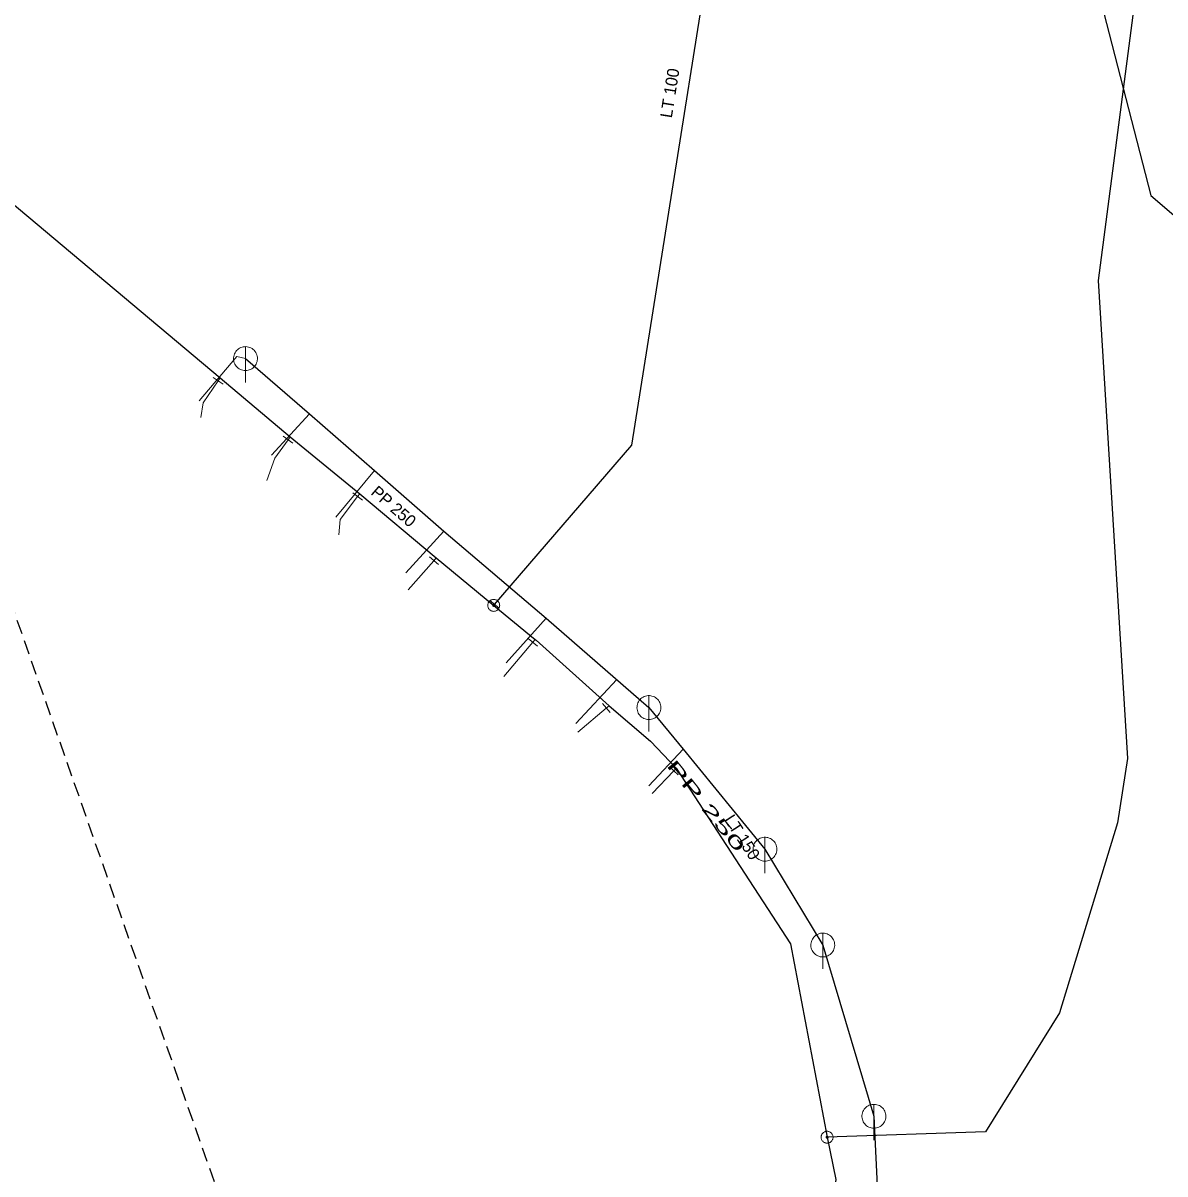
# Model space of a CAD drawing. Extents: x -659250 to -657316, y -997555 to -993684.
# Drawn here: x -658756.5 to -658660.9, y -994925.7 to -994829.4 of the extents above; entities that cross this region are included whole.
import ezdxf

# ---------------------------------------------------------------- set-up
doc = ezdxf.new("R2010")
doc.units = 0
doc.header["$LTSCALE"] = 0.4
doc.linetypes.add('MEDIUM_DASHED', pattern=[4.5, 3, -1.5])
doc.layers.add('1', color=7, linetype='Continuous')
for name, color, linetype, lineweight in [('11', 7, 'Continuous', 13), ('13', 7, 'Continuous', 13), ('14', 7, 'Continuous', 25), ('17', 7, 'Continuous', 25), ('22', 7, 'Continuous', 13), ('34', 7, 'Continuous', 13), ('47', 7, 'Continuous', 13), ('63', 7, 'MEDIUM_DASHED', 25)]:
    doc.layers.add(name, color=color, linetype=linetype, lineweight=lineweight)

msp = doc.modelspace()

# ---------------------------------------------------------------- linework, layer by layer
at = {"layer": '11'}
for p, q in [((-658735.68, -994865.6), (-658732.5, -994862.149)), ((-658730.28, -994870.78), (-658727.039, -994866.89)), ((-658724.43, -994875.46), (-658721.237, -994871.947)), ((-658716.03, -994882.969), (-658712.682, -994879.243)), ((-658706.775, -994884.377), (-658710.19, -994888.059)), ((-658704.1, -994893.28), (-658701.228, -994890.199))]:
    msp.add_line(p, q, dxfattribs=at)
msp.add_lwpolyline([(-658741.719, -994861.05), (-658738.559, -994857.35), (-658737.85, -994857.52)], dxfattribs=at)
at = {"layer": '13'}
for p, q in [((-658722.078, -994874.43), (-658724.219, -994876.859)), ((-658713.803, -994881.249), (-658716.219, -994884.129)), ((-658707.648, -994886.764), (-658710.03, -994888.789)), ((-658702.006, -994892.017), (-658703.8, -994893.91))]:
    msp.add_line(p, q, dxfattribs=at)
for points in [[(-658740.128, -994859.373), (-658741.39, -994861.234), (-658741.59, -994862.44)], [(-658734.276, -994864.307), (-658735.39, -994865.842), (-658736.05, -994867.719)], [(-658728.461, -994869.063), (-658729.916, -994870.975), (-658730.03, -994872.26)]]:
    msp.add_lwpolyline(points, dxfattribs=at)
at = {"layer": '14', "lineweight": 13}
for p, q in [((-658739.96, -994859.124), (-658740.128, -994859.373)), ((-658734.1, -994864.064), (-658734.276, -994864.307)), ((-658728.28, -994868.824), (-658728.461, -994869.063)), ((-658721.879, -994874.204), (-658722.078, -994874.43)), ((-658717.07, -994878.168), (-658717.005, -994878.092)), ((-658713.611, -994881.019), (-658713.803, -994881.249)), ((-658707.42, -994886.57), (-658707.648, -994886.764)), ((-658701.8, -994891.8), (-658702.006, -994892.017))]:
    msp.add_line(p, q, dxfattribs=at)
at = {"layer": '14'}
msp.add_line((-658685.25, -994920.92), (-658684.84, -994929.449), dxfattribs=at)
for points in [[(-658737.85, -994857.52), (-658732.5, -994862.149), (-658727.039, -994866.89), (-658721.237, -994871.947), (-658712.682, -994879.243), (-658704.079, -994886.719)], [(-658704.079, -994886.719), (-658701.228, -994890.199), (-658694.37, -994898.57)], [(-658694.37, -994898.57), (-658689.53, -994906.59), (-658685.25, -994920.92)]]:
    msp.add_lwpolyline(points, dxfattribs=at)
at = {"layer": '17'}
for points in [[(-658702.57, -994435.41), (-658705.199, -994436.353), (-658712.71, -994474.592), (-658701.204, -994536.879), (-658692.771, -994555.022), (-658691.405, -994641.16), (-658677.627, -994701.215), (-658678.449, -994734.261), (-658664.614, -994780.175), (-658662.973, -994794.498), (-658662.386, -994819.574), (-658666.489, -994850.982), (-658664.028, -994890.978), (-658664.848, -994896.368), (-658669.708, -994912.272), (-658675.921, -994922.23), (-658689.166, -994922.67)], [(-658833.469, -994620.44), (-658786.396, -994668.37), (-658672.524, -994803.272), (-658662.072, -994843.868), (-658638.662, -994863.933)], [(-658944.471, -994767.595), (-658929.982, -994769.565), (-658923.066, -994770.504), (-658908.315, -994773.538), (-658887.522, -994777.767), (-658868.1, -994785.67), (-658835.011, -994798.656), (-658813.55, -994808.542), (-658788.769, -994821.229), (-658774.498, -994830.239), (-658768.436, -994835.283), (-658761.23, -994841.315), (-658739.96, -994859.124), (-658734.1, -994864.064), (-658728.28, -994868.824), (-658721.879, -994874.204), (-658717.07, -994878.168)], [(-658717.005, -994878.092), (-658705.507, -994864.76), (-658695.942, -994804.489)], [(-658717.07, -994878.168), (-658713.611, -994881.019), (-658713.523, -994881.091), (-658707.42, -994886.57), (-658703.946, -994889.54), (-658701.8, -994891.8), (-658692.227, -994906.488), (-658689.166, -994922.67)], [(-658689.166, -994922.67), (-658688.447, -994926.223), (-658691.355, -994947.704), (-658699.204, -994963.84), (-658705.204, -994963.234), (-658707.419, -994974.603)]]:
    msp.add_lwpolyline(points, dxfattribs=at)
at = {"layer": '22'}
for p, q in [((-658737.85, -994859.52), (-658737.849, -994856.52)), ((-658704.08, -994888.72), (-658704.079, -994885.72)), ((-658694.37, -994900.57), (-658694.369, -994897.57)), ((-658689.53, -994908.59), (-658689.529, -994905.59)), ((-658685.25, -994922.92), (-658685.249, -994919.92))]:
    msp.add_line(p, q, dxfattribs=at)
for points in [[(-658736.85, -994857.52), (-658736.855, -994857.411), (-658736.873, -994857.303), (-658736.903, -994857.197), (-658736.943, -994857.096), (-658736.995, -994856.999), (-658737.057, -994856.909), (-658737.129, -994856.826), (-658737.209, -994856.752), (-658737.297, -994856.686), (-658737.391, -994856.631), (-658737.491, -994856.586), (-658737.596, -994856.553), (-658737.703, -994856.531), (-658737.812, -994856.521), (-658737.922, -994856.523), (-658738.03, -994856.537), (-658738.137, -994856.562), (-658738.24, -994856.599), (-658738.338, -994856.648), (-658738.43, -994856.706), (-658738.516, -994856.775), (-658738.593, -994856.852), (-658738.662, -994856.938), (-658738.721, -994857.03), (-658738.769, -994857.128), (-658738.806, -994857.231), (-658738.832, -994857.338), (-658738.846, -994857.446), (-658738.849, -994857.556), (-658738.839, -994857.665), (-658738.818, -994857.772), (-658738.784, -994857.876), (-658738.74, -994857.976), (-658738.685, -994858.071), (-658738.619, -994858.159), (-658738.545, -994858.239), (-658738.462, -994858.311), (-658738.372, -994858.373), (-658738.276, -994858.425), (-658738.174, -994858.466), (-658738.069, -994858.496), (-658737.961, -994858.514), (-658737.851, -994858.52), (-658737.742, -994858.514), (-658737.634, -994858.496), (-658737.529, -994858.467), (-658737.427, -994858.426), (-658737.33, -994858.374), (-658737.24, -994858.312), (-658737.157, -994858.241), (-658737.082, -994858.161), (-658737.017, -994858.073), (-658736.961, -994857.979), (-658736.917, -994857.879), (-658736.883, -994857.775), (-658736.861, -994857.667), (-658736.851, -994857.558)], [(-658703.08, -994886.72), (-658703.085, -994886.611), (-658703.103, -994886.503), (-658703.133, -994886.397), (-658703.173, -994886.296), (-658703.225, -994886.199), (-658703.287, -994886.109), (-658703.359, -994886.026), (-658703.439, -994885.952), (-658703.527, -994885.886), (-658703.621, -994885.831), (-658703.721, -994885.786), (-658703.826, -994885.753), (-658703.933, -994885.731), (-658704.042, -994885.721), (-658704.152, -994885.723), (-658704.26, -994885.737), (-658704.367, -994885.762), (-658704.47, -994885.799), (-658704.568, -994885.848), (-658704.66, -994885.906), (-658704.746, -994885.975), (-658704.823, -994886.052), (-658704.892, -994886.138), (-658704.951, -994886.23), (-658704.999, -994886.328), (-658705.036, -994886.431), (-658705.062, -994886.538), (-658705.076, -994886.646), (-658705.079, -994886.756), (-658705.069, -994886.865), (-658705.048, -994886.972), (-658705.014, -994887.076), (-658704.97, -994887.176), (-658704.915, -994887.271), (-658704.849, -994887.359), (-658704.775, -994887.439), (-658704.692, -994887.511), (-658704.602, -994887.573), (-658704.506, -994887.625), (-658704.404, -994887.666), (-658704.299, -994887.696), (-658704.191, -994887.714), (-658704.081, -994887.72), (-658703.972, -994887.714), (-658703.864, -994887.696), (-658703.759, -994887.667), (-658703.657, -994887.626), (-658703.56, -994887.574), (-658703.47, -994887.512), (-658703.387, -994887.441), (-658703.312, -994887.361), (-658703.247, -994887.273), (-658703.191, -994887.179), (-658703.147, -994887.079), (-658703.113, -994886.975), (-658703.091, -994886.867), (-658703.081, -994886.758)], [(-658693.37, -994898.57), (-658693.375, -994898.461), (-658693.393, -994898.353), (-658693.423, -994898.247), (-658693.463, -994898.146), (-658693.515, -994898.049), (-658693.577, -994897.959), (-658693.649, -994897.876), (-658693.729, -994897.802), (-658693.817, -994897.736), (-658693.911, -994897.681), (-658694.011, -994897.636), (-658694.116, -994897.603), (-658694.223, -994897.581), (-658694.332, -994897.571), (-658694.442, -994897.573), (-658694.55, -994897.587), (-658694.657, -994897.612), (-658694.76, -994897.649), (-658694.858, -994897.698), (-658694.95, -994897.756), (-658695.036, -994897.825), (-658695.113, -994897.902), (-658695.182, -994897.988), (-658695.241, -994898.08), (-658695.289, -994898.178), (-658695.326, -994898.281), (-658695.352, -994898.388), (-658695.366, -994898.496), (-658695.369, -994898.606), (-658695.359, -994898.715), (-658695.338, -994898.822), (-658695.304, -994898.926), (-658695.26, -994899.026), (-658695.205, -994899.121), (-658695.139, -994899.209), (-658695.065, -994899.289), (-658694.982, -994899.361), (-658694.892, -994899.423), (-658694.796, -994899.475), (-658694.694, -994899.516), (-658694.589, -994899.546), (-658694.481, -994899.564), (-658694.371, -994899.57), (-658694.262, -994899.564), (-658694.154, -994899.546), (-658694.049, -994899.517), (-658693.947, -994899.476), (-658693.85, -994899.424), (-658693.76, -994899.362), (-658693.677, -994899.291), (-658693.602, -994899.211), (-658693.537, -994899.123), (-658693.481, -994899.029), (-658693.437, -994898.929), (-658693.403, -994898.825), (-658693.381, -994898.717), (-658693.371, -994898.608)], [(-658688.53, -994906.59), (-658688.535, -994906.481), (-658688.553, -994906.373), (-658688.583, -994906.267), (-658688.623, -994906.166), (-658688.675, -994906.069), (-658688.737, -994905.979), (-658688.809, -994905.896), (-658688.889, -994905.822), (-658688.977, -994905.756), (-658689.071, -994905.701), (-658689.171, -994905.656), (-658689.276, -994905.623), (-658689.383, -994905.601), (-658689.492, -994905.591), (-658689.602, -994905.593), (-658689.71, -994905.607), (-658689.817, -994905.632), (-658689.92, -994905.669), (-658690.018, -994905.718), (-658690.11, -994905.776), (-658690.196, -994905.845), (-658690.273, -994905.922), (-658690.342, -994906.008), (-658690.401, -994906.1), (-658690.449, -994906.198), (-658690.486, -994906.301), (-658690.512, -994906.408), (-658690.526, -994906.516), (-658690.529, -994906.626), (-658690.519, -994906.735), (-658690.498, -994906.842), (-658690.464, -994906.946), (-658690.42, -994907.046), (-658690.365, -994907.141), (-658690.299, -994907.229), (-658690.225, -994907.309), (-658690.142, -994907.381), (-658690.052, -994907.443), (-658689.956, -994907.495), (-658689.854, -994907.536), (-658689.749, -994907.566), (-658689.641, -994907.584), (-658689.531, -994907.59), (-658689.422, -994907.584), (-658689.314, -994907.566), (-658689.209, -994907.537), (-658689.107, -994907.496), (-658689.01, -994907.444), (-658688.92, -994907.382), (-658688.837, -994907.311), (-658688.762, -994907.231), (-658688.697, -994907.143), (-658688.641, -994907.049), (-658688.597, -994906.949), (-658688.563, -994906.845), (-658688.541, -994906.737), (-658688.531, -994906.628)], [(-658684.25, -994920.92), (-658684.255, -994920.811), (-658684.273, -994920.703), (-658684.303, -994920.597), (-658684.343, -994920.496), (-658684.395, -994920.399), (-658684.457, -994920.309), (-658684.529, -994920.226), (-658684.609, -994920.152), (-658684.697, -994920.086), (-658684.791, -994920.031), (-658684.891, -994919.986), (-658684.996, -994919.953), (-658685.103, -994919.931), (-658685.212, -994919.921), (-658685.322, -994919.923), (-658685.43, -994919.937), (-658685.537, -994919.962), (-658685.64, -994919.999), (-658685.738, -994920.048), (-658685.83, -994920.106), (-658685.916, -994920.175), (-658685.993, -994920.252), (-658686.062, -994920.338), (-658686.121, -994920.43), (-658686.169, -994920.528), (-658686.206, -994920.631), (-658686.232, -994920.738), (-658686.246, -994920.846), (-658686.249, -994920.956), (-658686.239, -994921.065), (-658686.218, -994921.172), (-658686.184, -994921.276), (-658686.14, -994921.376), (-658686.085, -994921.471), (-658686.019, -994921.559), (-658685.945, -994921.639), (-658685.862, -994921.711), (-658685.772, -994921.773), (-658685.676, -994921.825), (-658685.574, -994921.866), (-658685.469, -994921.896), (-658685.361, -994921.914), (-658685.251, -994921.92), (-658685.142, -994921.914), (-658685.034, -994921.896), (-658684.929, -994921.867), (-658684.827, -994921.826), (-658684.73, -994921.774), (-658684.64, -994921.712), (-658684.557, -994921.641), (-658684.482, -994921.561), (-658684.417, -994921.473), (-658684.361, -994921.379), (-658684.317, -994921.279), (-658684.283, -994921.175), (-658684.261, -994921.067), (-658684.251, -994920.958)]]:
    msp.add_lwpolyline(points, close=True, dxfattribs=at)
at = {"layer": '34'}
for p, q in [((-658739.713, -994859.653), (-658740.541, -994859.092)), ((-658733.871, -994864.6), (-658734.68, -994864.012)), ((-658728.062, -994869.365), (-658728.858, -994868.759)), ((-658721.702, -994874.76), (-658722.452, -994874.099)), ((-658717.386, -994877.769), (-658716.623, -994878.415)), ((-658713.419, -994881.569), (-658714.185, -994880.927)), ((-658707.323, -994887.144), (-658707.971, -994886.382)), ((-658701.642, -994892.36), (-658702.368, -994891.672))]:
    msp.add_line(p, q, dxfattribs=at)
at = {"layer": '47'}
for points in [[(-658716.57, -994878.168), (-658716.573, -994878.115), (-658716.581, -994878.063), (-658716.595, -994878.014), (-658716.612, -994877.965), (-658716.637, -994877.918), (-658716.666, -994877.874), (-658716.698, -994877.833), (-658716.735, -994877.796), (-658716.776, -994877.764), (-658716.82, -994877.735), (-658716.867, -994877.71), (-658716.916, -994877.693), (-658716.965, -994877.679), (-658717.017, -994877.671), (-658717.07, -994877.668), (-658717.122, -994877.671), (-658717.174, -994877.679), (-658717.225, -994877.693), (-658717.272, -994877.71), (-658717.32, -994877.735), (-658717.364, -994877.764), (-658717.404, -994877.796), (-658717.441, -994877.833), (-658717.475, -994877.874), (-658717.502, -994877.918), (-658717.527, -994877.965), (-658717.546, -994878.014), (-658717.558, -994878.063), (-658717.566, -994878.115), (-658717.57, -994878.168), (-658717.566, -994878.22), (-658717.558, -994878.272), (-658717.546, -994878.323), (-658717.527, -994878.37), (-658717.502, -994878.418), (-658717.475, -994878.462), (-658717.441, -994878.502), (-658717.404, -994878.539), (-658717.364, -994878.573), (-658717.32, -994878.6), (-658717.272, -994878.625), (-658717.225, -994878.644), (-658717.174, -994878.656), (-658717.122, -994878.664), (-658717.07, -994878.668), (-658717.017, -994878.664), (-658716.965, -994878.656), (-658716.916, -994878.644), (-658716.867, -994878.625), (-658716.82, -994878.6), (-658716.776, -994878.573), (-658716.735, -994878.539), (-658716.698, -994878.502), (-658716.666, -994878.462), (-658716.637, -994878.418), (-658716.612, -994878.37), (-658716.595, -994878.323), (-658716.581, -994878.272), (-658716.573, -994878.22)], [(-658716.987, -994878.168), (-658716.987, -994878.159), (-658716.99, -994878.151), (-658716.992, -994878.142), (-658716.995, -994878.134), (-658716.999, -994878.127), (-658717.004, -994878.12), (-658717.009, -994878.112), (-658717.014, -994878.107), (-658717.022, -994878.102), (-658717.029, -994878.097), (-658717.036, -994878.093), (-658717.044, -994878.09), (-658717.053, -994878.088), (-658717.061, -994878.085), (-658717.07, -994878.085), (-658717.078, -994878.085), (-658717.087, -994878.088), (-658717.095, -994878.09), (-658717.103, -994878.093), (-658717.11, -994878.097), (-658717.117, -994878.102), (-658717.125, -994878.107), (-658717.13, -994878.112), (-658717.137, -994878.12), (-658717.141, -994878.127), (-658717.144, -994878.134), (-658717.147, -994878.142), (-658717.149, -994878.151), (-658717.152, -994878.159), (-658717.152, -994878.168), (-658717.152, -994878.176), (-658717.149, -994878.184), (-658717.147, -994878.193), (-658717.144, -994878.201), (-658717.141, -994878.208), (-658717.137, -994878.215), (-658717.13, -994878.223), (-658717.125, -994878.228), (-658717.117, -994878.235), (-658717.11, -994878.239), (-658717.103, -994878.242), (-658717.095, -994878.245), (-658717.087, -994878.247), (-658717.078, -994878.25), (-658717.07, -994878.25), (-658717.061, -994878.25), (-658717.053, -994878.247), (-658717.044, -994878.245), (-658717.036, -994878.242), (-658717.029, -994878.239), (-658717.022, -994878.235), (-658717.014, -994878.228), (-658717.009, -994878.223), (-658717.004, -994878.215), (-658716.999, -994878.208), (-658716.995, -994878.201), (-658716.992, -994878.193), (-658716.99, -994878.184), (-658716.987, -994878.176)], [(-658688.666, -994922.67), (-658688.669, -994922.618), (-658688.677, -994922.566), (-658688.691, -994922.516), (-658688.708, -994922.467), (-658688.733, -994922.42), (-658688.762, -994922.376), (-658688.794, -994922.336), (-658688.831, -994922.299), (-658688.872, -994922.266), (-658688.916, -994922.237), (-658688.963, -994922.213), (-658689.012, -994922.195), (-658689.061, -994922.181), (-658689.114, -994922.173), (-658689.166, -994922.17), (-658689.218, -994922.173), (-658689.27, -994922.181), (-658689.321, -994922.195), (-658689.369, -994922.213), (-658689.416, -994922.237), (-658689.46, -994922.266), (-658689.5, -994922.299), (-658689.538, -994922.336), (-658689.571, -994922.376), (-658689.598, -994922.42), (-658689.623, -994922.467), (-658689.642, -994922.516), (-658689.654, -994922.566), (-658689.663, -994922.618), (-658689.666, -994922.67), (-658689.663, -994922.722), (-658689.654, -994922.774), (-658689.642, -994922.825), (-658689.623, -994922.873), (-658689.598, -994922.92), (-658689.571, -994922.964), (-658689.538, -994923.005), (-658689.5, -994923.042), (-658689.46, -994923.075), (-658689.416, -994923.103), (-658689.369, -994923.127), (-658689.321, -994923.146), (-658689.27, -994923.159), (-658689.218, -994923.167), (-658689.166, -994923.17), (-658689.114, -994923.167), (-658689.061, -994923.159), (-658689.012, -994923.146), (-658688.963, -994923.127), (-658688.916, -994923.103), (-658688.872, -994923.075), (-658688.831, -994923.042), (-658688.794, -994923.005), (-658688.762, -994922.964), (-658688.733, -994922.92), (-658688.708, -994922.873), (-658688.691, -994922.825), (-658688.677, -994922.774), (-658688.669, -994922.722)], [(-658689.083, -994922.67), (-658689.083, -994922.661), (-658689.086, -994922.653), (-658689.088, -994922.645), (-658689.091, -994922.637), (-658689.095, -994922.629), (-658689.1, -994922.622), (-658689.105, -994922.615), (-658689.11, -994922.609), (-658689.118, -994922.604), (-658689.125, -994922.599), (-658689.132, -994922.595), (-658689.141, -994922.592), (-658689.149, -994922.59), (-658689.157, -994922.588), (-658689.166, -994922.588), (-658689.174, -994922.588), (-658689.183, -994922.59), (-658689.191, -994922.592), (-658689.199, -994922.595), (-658689.206, -994922.599), (-658689.213, -994922.604), (-658689.221, -994922.609), (-658689.227, -994922.615), (-658689.233, -994922.622), (-658689.237, -994922.629), (-658689.24, -994922.637), (-658689.244, -994922.645), (-658689.245, -994922.653), (-658689.248, -994922.661), (-658689.248, -994922.67), (-658689.248, -994922.679), (-658689.245, -994922.687), (-658689.244, -994922.695), (-658689.24, -994922.703), (-658689.237, -994922.711), (-658689.233, -994922.718), (-658689.227, -994922.725), (-658689.221, -994922.731), (-658689.213, -994922.737), (-658689.206, -994922.741), (-658689.199, -994922.745), (-658689.191, -994922.748), (-658689.183, -994922.75), (-658689.174, -994922.752), (-658689.166, -994922.752), (-658689.157, -994922.752), (-658689.149, -994922.75), (-658689.141, -994922.748), (-658689.132, -994922.745), (-658689.125, -994922.741), (-658689.118, -994922.737), (-658689.11, -994922.731), (-658689.105, -994922.725), (-658689.1, -994922.718), (-658689.095, -994922.711), (-658689.091, -994922.703), (-658689.088, -994922.695), (-658689.086, -994922.687), (-658689.083, -994922.679)]]:
    msp.add_lwpolyline(points, close=True, dxfattribs=at)
at = {"layer": '63'}
msp.add_lwpolyline([(-659116.685, -993855.266), (-658551.464, -993848.288), (-658551.464, -993848.288), (-657316.352, -997490.822), (-657316.352, -997490.822), (-657839.705, -997490.822), (-657839.705, -997490.822)], close=True, dxfattribs=at)

# ---------------------------------------------------------------- texts
at = {"layer": '1'}
for s, rotation, p in [('LT 100', 81, (-658702.168, -994837.433)), ('PP 250', 319, (-658727.428, -994868.825)), ('LT 150', 303, (-658697.825, -994896.092))]:
    msp.add_text(s, height=1, rotation=rotation, dxfattribs=at).set_placement(p)
at = {"layer": '1', "width": 2.15}
msp.add_text('PP 250', height=1, rotation=309, dxfattribs=at).set_placement((-658702.662, -994891.582))

doc.saveas('drawing.dxf')
